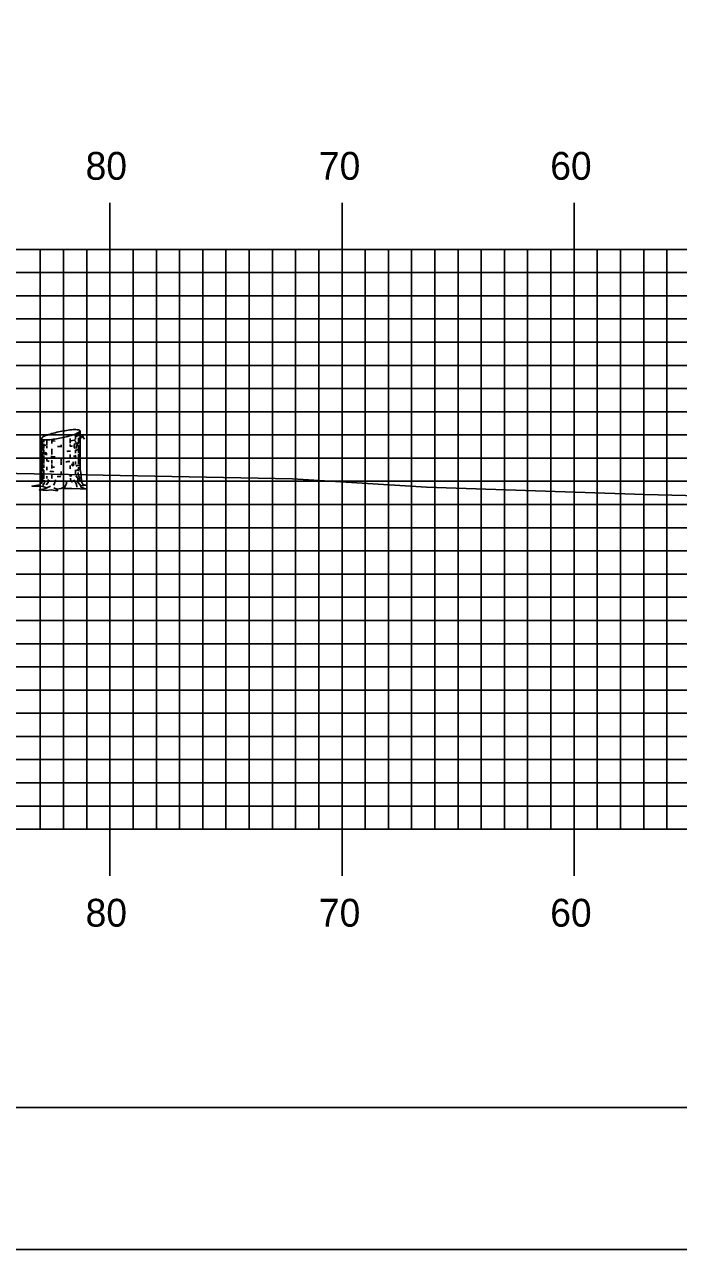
# Model space of a CAD drawing. Extents: x 1771235 to 1771579, y 442591 to 442811.
# Drawn here: x 1771317.4 to 1771345.6, y 442590.5 to 442643.4 of the extents above; entities that cross this region are included whole.
import ezdxf

# ---------------------------------------------------------------- set-up
doc = ezdxf.new("R2010")
doc.units = 0
for name, color, linetype in [('BORDER', 7, 'Continuous'), ('H_V ANNOTATION', 7, 'Continuous'), ('M_Trees_Conifer_Pay', 7, 'Continuous'), ('MAJOR', 7, 'Continuous'), ('MINOR', 7, 'Continuous'), ('PLOT BOUNDARY', 7, 'Continuous'), ('S_Roadway_Centerline', 7, 'Continuous')]:
    doc.layers.add(name, color=color, linetype=linetype)

msp = doc.modelspace()

# ---------------------------------------------------------------- linework, layer by layer
at = {"layer": 'BORDER'}
msp.add_lwpolyline([(1771251.467, 442596.665), (1771571.467, 442596.665), (1771571.467, 442806.665), (1771251.467, 442806.665)], close=True, dxfattribs=at)
at = {"layer": 'M_Trees_Conifer_Pay'}
for p, q in [((1771319.588, 442625.707), (1771319.588, 442625.484)), ((1771319.705, 442625.768), (1771319.705, 442625.605)), ((1771319.777, 442624.193), (1771319.777, 442625.84)), ((1771318.113, 442623.783), (1771318.113, 442625.505)), ((1771318.16, 442625.468), (1771318.16, 442624.996)), ((1771318.218, 442625.456), (1771318.218, 442625.359)), ((1771318.218, 442625.284), (1771318.218, 442625.08)), ((1771318.344, 442625.448), (1771318.344, 442625.216)), ((1771318.344, 442625.176), (1771318.344, 442625.101)), ((1771318.563, 442625.469), (1771318.563, 442625.301)), ((1771318.969, 442625.237), (1771318.969, 442625.142)), ((1771319.359, 442625.511), (1771319.359, 442625.311)), ((1771319.359, 442625.254), (1771319.359, 442625.165)), ((1771319.588, 442625.395), (1771319.588, 442625.348)), ((1771319.645, 442625.212), (1771319.594, 442625.153)), ((1771319.705, 442625.538), (1771319.705, 442625.41)), ((1771319.705, 442625.223), (1771319.705, 442624.887)), ((1771318.16, 442624.932), (1771318.16, 442624.624)), ((1771318.218, 442625.023), (1771318.218, 442624.823)), ((1771318.218, 442624.776), (1771318.218, 442624.44)), ((1771318.344, 442624.698), (1771318.344, 442624.559)), ((1771318.563, 442625.064), (1771318.563, 442624.827)), ((1771319.359, 442624.817), (1771319.359, 442624.712)), ((1771319.588, 442625.013), (1771319.588, 442624.881)), ((1771319.588, 442624.77), (1771319.588, 442624.66)), ((1771319.705, 442624.85), (1771319.705, 442624.687)), ((1771319.705, 442624.64), (1771319.705, 442624.424)), ((1771318.16, 442624.576), (1771318.16, 442624.084)), ((1771318.218, 442624.387), (1771318.218, 442624.251)), ((1771318.218, 442624.152), (1771318.218, 442623.773)), ((1771318.344, 442624.288), (1771318.344, 442624.146)), ((1771318.563, 442624.582), (1771318.563, 442624.43)), ((1771318.563, 442624.387), (1771318.563, 442624.214)), ((1771318.969, 442624.624), (1771318.969, 442624.55)), ((1771318.969, 442624.525), (1771318.969, 442624.376)), ((1771319.359, 442624.345), (1771319.359, 442624.199)), ((1771319.588, 442624.525), (1771319.588, 442624.383)), ((1771319.588, 442624.156), (1771319.588, 442623.983)), ((1771319.705, 442624.393), (1771319.705, 442624.319)), ((1771319.705, 442624.278), (1771319.705, 442624.105)), ((1771318.16, 442624.031), (1771318.16, 442623.783)), ((1771318.344, 442623.884), (1771318.344, 442623.79)), ((1771318.563, 442623.936), (1771318.563, 442623.783)), ((1771318.969, 442624.084), (1771318.969, 442623.931)), ((1771319.359, 442623.967), (1771319.359, 442623.878)), ((1771318.344, 442623.39), (1771318.506, 442623.454)), ((1771318.781, 442623.326), (1771318.655, 442623.39))]:
    msp.add_line(p, q, dxfattribs=at)
for points in [[(1771319.56, 442625.301), (1771319.529, 442625.216), (1771319.525, 442625.149), (1771319.556, 442625.085)], [(1771319.594, 442625.338), (1771319.63, 442625.264), (1771319.678, 442625.321), (1771319.735, 442625.389), (1771319.828, 442625.583), (1771319.892, 442625.63), (1771319.923, 442625.637)], [(1771319.608, 442625.085), (1771319.645, 442625.212), (1771319.708, 442625.328), (1771319.739, 442625.395), (1771319.808, 442625.542)], [(1771319.823, 442625.571), (1771319.898, 442625.579), (1771319.97, 442625.48)], [(1771318.292, 442624.811), (1771318.286, 442624.906), (1771318.329, 442624.883), (1771318.329, 442624.788)], [(1771319.777, 442624.193), (1771319.828, 442623.931), (1771319.844, 442623.658), (1771319.902, 442623.532), (1771320.038, 442623.502), (1771319.808, 442623.464), (1771319.808, 442623.464), (1771319.813, 442623.417), (1771320.061, 442623.322), (1771319.787, 442623.339), (1771319.431, 442623.359), (1771319.109, 442623.349), (1771319.116, 442623.431), (1771318.968, 442623.349), (1771318.781, 442623.326), (1771318.805, 442623.258), (1771318.537, 442623.302), (1771318.317, 442623.275), (1771318.024, 442623.292), (1771318.313, 442623.349), (1771318.344, 442623.39), (1771318.181, 442623.448), (1771317.944, 442623.458), (1771317.703, 442623.458), (1771318.045, 442623.516), (1771318.086, 442623.596), (1771318.113, 442623.783)], [(1771319.431, 442624.412), (1771319.443, 442624.335), (1771319.491, 442624.345), (1771319.478, 442624.512)], [(1771318.161, 442623.736), (1771318.14, 442623.658), (1771318.119, 442623.563)], [(1771318.239, 442623.716), (1771318.245, 442623.6), (1771318.191, 442623.511), (1771318.181, 442623.448)], [(1771318.401, 442623.742), (1771318.401, 442623.611), (1771318.313, 442623.511)], [(1771318.628, 442623.502), (1771318.695, 442623.596), (1771318.722, 442623.736)], [(1771319.116, 442623.431), (1771319.19, 442623.573), (1771319.2, 442623.674)], [(1771319.367, 442623.8), (1771319.377, 442623.674), (1771319.451, 442623.631)], [(1771319.645, 442623.411), (1771319.63, 442623.549), (1771319.556, 442623.678)], [(1771319.603, 442623.905), (1771319.678, 442623.8), (1771319.682, 442623.627), (1771319.808, 442623.464)], [(1771319.703, 442624.051), (1771319.708, 442623.905), (1771319.756, 442623.837), (1771319.766, 442623.637)]]:
    msp.add_lwpolyline(points, dxfattribs=at)
for centre, radius, start, end in [((1771319.969, 442620.737), 5.179, 101.7194, 108.0594), ((1771319.969, 442620.737), 5.179, 95.3794, 101.7194), ((1771319.558, 442625.095), 0.802, 79.2194, 95.3794), ((1771319.278, 442626.446), 0.802, 288.0594, 304.2194), ((1771319.661, 442625.637), 0.251, 71.0501, 79.2194), ((1771319.588, 442625.99), 0.251, 304.2194, 312.3887), ((1771319.716, 442625.796), 0.0817, 56.7194, 71.0501), ((1771319.702, 442625.866), 0.0817, 312.3887, 326.7194), ((1771319.717, 442625.726), 0.0624, 311.2506, 330), ((1771319.732, 442625.821), 0.0527, 46.923, 56.7194), ((1771319.747, 442625.836), 0.0314, 34.2194, 46.923), ((1771319.726, 442625.85), 0.0527, 326.7194, 336.5158), ((1771319.733, 442625.717), 0.0441, 330, 343.9485), ((1771319.751, 442625.839), 0.0264, 23.4074, 34.2194), ((1771319.745, 442625.841), 0.0314, 336.5158, 349.2194), ((1771319.754, 442625.84), 0.0226, 11.7194, 23.4074), ((1771319.754, 442625.84), 0.0226, 0.0315, 11.7194), ((1771319.75, 442625.84), 0.0264, 349.2194, 0.0315), ((1771319.744, 442625.714), 0.0334, 343.9485, 354.2151), ((1771318.145, 442625.327), 0.0334, 163.9485, 180), ((1771318.145, 442625.327), 0.0334, 180, 196.0515), ((1771318.144, 442625.504), 0.0314, 156.5158, 169.2194), ((1771318.139, 442625.505), 0.0264, 169.2194, 180.0315), ((1771318.135, 442625.505), 0.0226, 180.0315, 191.7194), ((1771318.135, 442625.505), 0.0226, 191.7194, 203.4074), ((1771318.155, 442625.33), 0.0441, 196.0515, 210), ((1771318.164, 442625.495), 0.0527, 146.7194, 156.5158), ((1771318.139, 442625.506), 0.0264, 203.4074, 214.2194), ((1771318.143, 442625.509), 0.0314, 214.2194, 226.923), ((1771318.171, 442625.339), 0.0624, 210, 228.7494), ((1771318.188, 442625.479), 0.0817, 132.3887, 146.7194), ((1771318.158, 442625.524), 0.0527, 226.923, 236.7194), ((1771318.173, 442625.549), 0.0817, 236.7194, 251.0501), ((1771318.243, 442625.421), 0.172, 228.7494, 240), ((1771318.302, 442625.355), 0.251, 124.2194, 132.3887), ((1771318.228, 442625.708), 0.251, 251.0501, 259.2194), ((1771318.443, 442625.766), 0.571, 240, 240.3367), ((1771318.612, 442624.899), 0.802, 108.0594, 124.2194), ((1771318.331, 442626.25), 0.802, 259.2194, 275.3794), ((1771318.443, 442625.766), 0.571, 246.8597, 257.9846), ((1771317.921, 442630.608), 5.179, 275.3794, 281.7194), ((1771318.945, 442629.517), 4.124, 264.6955, 266.7331), ((1771318.943, 442629.284), 4.124, 268.0751, 270), ((1771318.943, 442629.284), 4.124, 270, 270.3581), ((1771317.921, 442630.608), 5.179, 281.7194, 288.0594), ((1771318.943, 442629.284), 4.124, 275.7849, 277.0558), ((1771318.945, 442629.517), 4.124, 276.238, 278.1032), ((1771319.446, 442625.999), 0.571, 278.1032, 284.3667), ((1771319.446, 442626.154), 0.571, 284.4317, 292.4132), ((1771319.446, 442625.999), 0.571, 297.0237, 300), ((1771319.645, 442625.809), 0.172, 300, 311.2506), ((1771319.645, 442625.654), 0.172, 300, 311.2506), ((1771319.717, 442625.572), 0.0624, 311.2506, 330), ((1771319.733, 442625.563), 0.0441, 330, 343.9485), ((1771319.744, 442625.56), 0.0334, 343.9485, 354.2151), ((1771318.145, 442624.88), 0.0334, 163.9485, 180), ((1771318.145, 442624.88), 0.0334, 180, 196.0515), ((1771318.145, 442624.67), 0.0334, 163.9485, 180), ((1771318.145, 442624.67), 0.0334, 180, 196.0515), ((1771318.155, 442624.883), 0.0441, 196.0515, 210), ((1771318.155, 442624.673), 0.0441, 196.0515, 210), ((1771318.171, 442624.892), 0.0624, 210, 228.7494), ((1771318.171, 442624.682), 0.0624, 210, 228.7494), ((1771318.243, 442624.975), 0.172, 228.7494, 240), ((1771318.243, 442624.765), 0.172, 228.7494, 240), ((1771318.443, 442625.32), 0.571, 240, 240.3367), ((1771318.444, 442625.555), 0.571, 240, 247.0587), ((1771318.943, 442628.837), 4.124, 264.081, 266.6676), ((1771318.945, 442629.073), 4.124, 273.7052, 275.9504), ((1771318.943, 442628.837), 4.124, 277.6125, 278.1032), ((1771319.444, 442625.32), 0.571, 278.1032, 286.9296), ((1771319.446, 442625.555), 0.571, 284.4493, 297.0429), ((1771319.444, 442625.32), 0.571, 297.1896, 300), ((1771319.644, 442624.975), 0.172, 300, 311.2506), ((1771319.644, 442624.765), 0.172, 300, 311.2506), ((1771319.716, 442624.892), 0.0624, 311.2506, 330), ((1771319.716, 442624.682), 0.0624, 311.2506, 330), ((1771319.732, 442624.883), 0.0441, 330, 343.9485), ((1771319.732, 442624.673), 0.0441, 330, 343.9485), ((1771319.742, 442624.88), 0.0334, 343.9485, 354.2151), ((1771319.742, 442624.67), 0.0334, 343.9485, 354.2151), ((1771319.743, 442625.116), 0.0334, 343.9485, 354.2151), ((1771318.145, 442624.433), 0.0334, 163.9485, 180), ((1771318.145, 442624.433), 0.0334, 180, 196.0515), ((1771318.145, 442624.235), 0.0334, 163.9485, 180), ((1771318.155, 442624.436), 0.0441, 196.0515, 210), ((1771318.171, 442624.445), 0.0624, 210, 228.7494), ((1771318.243, 442624.528), 0.172, 228.7494, 240), ((1771318.443, 442625.11), 0.571, 240, 246.8597), ((1771318.443, 442624.873), 0.571, 240, 246.8597), ((1771318.432, 442624.681), 0.571, 241.2369, 248.0268), ((1771318.443, 442625.11), 0.571, 259.2707, 261.8968), ((1771318.943, 442628.627), 4.124, 261.8968, 263.1474), ((1771318.943, 442628.39), 4.124, 264.716, 266.3193), ((1771318.943, 442628.627), 4.124, 270, 270.3581), ((1771318.943, 442628.627), 4.124, 273.1493, 275.4569), ((1771319.444, 442624.873), 0.571, 285.3983, 297.1896), ((1771319.444, 442624.675), 0.571, 289.2907, 300), ((1771319.444, 442625.11), 0.571, 297.1896, 300), ((1771319.644, 442624.33), 0.172, 300, 311.2506), ((1771319.716, 442624.248), 0.0624, 311.2506, 330), ((1771319.732, 442624.238), 0.0441, 330, 343.9485), ((1771319.742, 442624.235), 0.0334, 343.9485, 354.2151), ((1771318.145, 442624.04), 0.0334, 163.9485, 180), ((1771318.145, 442624.04), 0.0334, 180, 196.0515), ((1771318.145, 442623.819), 0.0334, 163.9485, 180), ((1771318.145, 442623.819), 0.0334, 180, 196.0515), ((1771318.155, 442624.043), 0.0441, 196.0515, 210), ((1771318.155, 442623.822), 0.0441, 196.0515, 210), ((1771318.171, 442624.052), 0.0624, 210, 228.7494), ((1771318.171, 442623.832), 0.0624, 210, 228.7494), ((1771318.243, 442624.135), 0.172, 228.7494, 240), ((1771318.243, 442623.914), 0.172, 228.7494, 240), ((1771318.443, 442624.48), 0.571, 240, 246.8597), ((1771318.443, 442624.259), 0.571, 240, 244.5314), ((1771318.943, 442627.777), 4.124, 262.4438, 263.512), ((1771318.943, 442628.193), 4.124, 263.4991, 265.8397), ((1771318.943, 442627.997), 4.124, 267.8117, 270), ((1771318.943, 442627.997), 4.124, 270, 270.1328), ((1771318.943, 442627.997), 4.124, 275.7849, 276.7896), ((1771318.943, 442627.777), 4.124, 277.3684, 278.1032), ((1771319.444, 442624.259), 0.571, 278.1032, 281.637), ((1771319.444, 442624.48), 0.571, 288.5067, 297.2721), ((1771319.644, 442623.914), 0.172, 300, 311.2506), ((1771319.716, 442623.832), 0.0624, 311.2506, 330), ((1771319.732, 442623.822), 0.0441, 330, 343.9485), ((1771319.742, 442623.819), 0.0334, 343.9485, 354.2151)]:
    msp.add_arc(centre, radius, start, end, dxfattribs=at)
at = {"layer": 'MAJOR'}
for p, q in [((1771321.067, 442635.669), (1771321.067, 442633.665)), ((1771331.067, 442635.669), (1771331.067, 442633.665)), ((1771341.067, 442635.669), (1771341.067, 442633.665)), ((1771261.067, 442633.665), (1771541.067, 442633.665)), ((1771261.067, 442633.665), (1771541.067, 442633.665)), ((1771321.067, 442608.665), (1771321.067, 442633.665)), ((1771331.067, 442608.665), (1771331.067, 442633.665)), ((1771341.067, 442608.665), (1771341.067, 442633.665)), ((1771261.067, 442628.665), (1771541.067, 442628.665)), ((1771261.067, 442623.665), (1771541.067, 442623.665)), ((1771261.067, 442618.665), (1771541.067, 442618.665)), ((1771261.067, 442613.665), (1771541.067, 442613.665)), ((1771261.067, 442608.665), (1771541.067, 442608.665)), ((1771261.067, 442608.665), (1771541.067, 442608.665)), ((1771321.067, 442606.661), (1771321.067, 442608.665)), ((1771331.067, 442606.661), (1771331.067, 442608.665)), ((1771341.067, 442606.661), (1771341.067, 442608.665))]:
    msp.add_line(p, q, dxfattribs=at)
at = {"layer": 'MINOR'}
for p, q in [((1771318.067, 442608.665), (1771318.067, 442633.665)), ((1771319.067, 442608.665), (1771319.067, 442633.665)), ((1771320.067, 442608.665), (1771320.067, 442633.665)), ((1771322.067, 442608.665), (1771322.067, 442633.665)), ((1771323.067, 442608.665), (1771323.067, 442633.665)), ((1771324.067, 442608.665), (1771324.067, 442633.665)), ((1771325.067, 442608.665), (1771325.067, 442633.665)), ((1771326.067, 442608.665), (1771326.067, 442633.665)), ((1771327.067, 442608.665), (1771327.067, 442633.665)), ((1771328.067, 442608.665), (1771328.067, 442633.665)), ((1771329.067, 442608.665), (1771329.067, 442633.665)), ((1771330.067, 442608.665), (1771330.067, 442633.665)), ((1771332.067, 442608.665), (1771332.067, 442633.665)), ((1771333.067, 442608.665), (1771333.067, 442633.665)), ((1771334.067, 442608.665), (1771334.067, 442633.665)), ((1771335.067, 442608.665), (1771335.067, 442633.665)), ((1771336.067, 442608.665), (1771336.067, 442633.665)), ((1771337.067, 442608.665), (1771337.067, 442633.665)), ((1771338.067, 442608.665), (1771338.067, 442633.665)), ((1771339.067, 442608.665), (1771339.067, 442633.665)), ((1771340.067, 442608.665), (1771340.067, 442633.665)), ((1771342.067, 442608.665), (1771342.067, 442633.665)), ((1771343.067, 442608.665), (1771343.067, 442633.665)), ((1771344.067, 442608.665), (1771344.067, 442633.665)), ((1771345.067, 442608.665), (1771345.067, 442633.665)), ((1771261.067, 442632.665), (1771541.067, 442632.665)), ((1771261.067, 442631.665), (1771541.067, 442631.665)), ((1771261.067, 442630.665), (1771541.067, 442630.665)), ((1771261.067, 442629.665), (1771541.067, 442629.665)), ((1771261.067, 442627.665), (1771541.067, 442627.665)), ((1771261.067, 442626.665), (1771541.067, 442626.665)), ((1771261.067, 442625.665), (1771541.067, 442625.665)), ((1771261.067, 442624.665), (1771541.067, 442624.665)), ((1771261.067, 442622.665), (1771541.067, 442622.665)), ((1771261.067, 442621.665), (1771541.067, 442621.665)), ((1771261.067, 442620.665), (1771541.067, 442620.665)), ((1771261.067, 442619.665), (1771541.067, 442619.665)), ((1771261.067, 442617.665), (1771541.067, 442617.665)), ((1771261.067, 442616.665), (1771541.067, 442616.665)), ((1771261.067, 442615.665), (1771541.067, 442615.665)), ((1771261.067, 442614.665), (1771541.067, 442614.665)), ((1771261.067, 442612.665), (1771541.067, 442612.665)), ((1771261.067, 442611.665), (1771541.067, 442611.665)), ((1771261.067, 442610.665), (1771541.067, 442610.665)), ((1771261.067, 442609.665), (1771541.067, 442609.665))]:
    msp.add_line(p, q, dxfattribs=at)
at = {"layer": 'PLOT BOUNDARY'}
msp.add_lwpolyline([(1771235.281, 442590.547), (1771575.281, 442590.547), (1771575.281, 442810.547), (1771235.281, 442810.547)], close=True, dxfattribs=at)
at = {"layer": 'S_Roadway_Centerline'}
msp.add_lwpolyline([(1771261.067, 442625.671), (1771263.095, 442625.617), (1771268.422, 442625.35), (1771275.522, 442625.038), (1771285.624, 442624.666), (1771286.784, 442624.651), (1771287.698, 442624.665), (1771298.589, 442624.703), (1771309.404, 442624.118), (1771311.113, 442624.118), (1771313.33, 442624.077), (1771328.929, 442623.769), (1771334.708, 442623.416), (1771344.096, 442623.092), (1771347.049, 442623.018)], dxfattribs=at)

# ---------------------------------------------------------------- texts
at = {"layer": 'H_V ANNOTATION'}
for s, p in [('80', (1771320.018, 442636.665)), ('70', (1771330.072, 442636.665)), ('60', (1771340.04, 442636.665)), ('80', (1771320.018, 442604.465)), ('70', (1771330.072, 442604.465)), ('60', (1771340.04, 442604.465))]:
    msp.add_text(s, height=1.2, dxfattribs=at).set_placement(p)

doc.saveas('drawing.dxf')
